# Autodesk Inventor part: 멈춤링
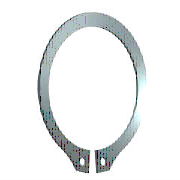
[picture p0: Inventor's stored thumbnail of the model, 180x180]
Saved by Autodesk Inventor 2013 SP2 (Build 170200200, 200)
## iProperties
IsCustomPart: 0
Created: 2009-02
Part Number: 멈춤링
Material: 강, 연강
Description: 리테이닝 링(C형)
Document SubType Name: Modeling
Standard: KS B 1336
Designer: KYOUNG IL JANG
Standards Organization: KS
Language: ko-KR
Size Designation: 22 x 1.2
Categories: <MemberInstance><Categories><Category DisplayName="샤프트 부품" InternalName="7f7aeb1f-a693-4053-b835-cee3144e0d98" Mnemonic="SHFT"><Category DisplayName="써클립" Inter
Density: 1 g/cm^3
Author: KYOUNG IL JANG
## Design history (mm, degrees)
sketch "스케치1"
  geometry: L1 (-6, 0)-(6, 0) reference; L2 (0, 20.189)-(0, -80.536) reference; L3 (-48.09, 0)-(48.09, 0) reference; L4 (-0.5, -21.488)-(-0.5, -25.588); L5 (-0.5, -6.54)-(-0.5, -13.29); L6 (-2.795, 2.7)-(3.672, 2.7); L7 (0.5, -6.54)-(0.5, -13.29); L8 (0.5, -21.488)-(0.5, -25.588); C1 r 1 at (-2, -23.437); C2 r 1 at (2, -23.437); A1 r 10.5 centre (0, -11) between (0.5, -21.488) and (-0.5, -21.488); A2 r 13.025 centre (0, -10.325) between (5.149, -22.289) and (-5.149, -22.289); A3 r 14.597 centre (0, -11) between (-2.318, -25.411) and (-0.5, -25.588); A4 r 2 centre (-2, -23.437) between (-3.97, -23.781) and (-2.318, -25.411); A5 r 2 centre (-5.94, -24.126) between (-3.97, -23.781) and (-5.149, -22.289); A6 r 2 centre (5.94, -24.126) between (5.149, -22.289) and (3.97, -23.781); A7 r 2 centre (2, -23.437) between (2.318, -25.411) and (3.97, -23.781); A8 r 14.597 centre (0, -11) between (0.5, -25.588) and (2.318, -25.411)
  constraints: 16 point on circle, 12 end point, 10 centre point, 9 symmetric about line, 5 point on line, 4 tangent, 3 coincident, 2 horizontal, 1 perpendicular, 1 vertical, 5 other
  dimensions: "d0" = 21 diameter of A1 (= ND); "d1" = 4.1 distance of L4.end L4.start (= SRB2); "d6" = 0.5 distance between parallel lines of L2 L5 (= 0.25 x SD5); "d7" = 2.7 distance between parallel lines of L6 L3 (= SRB1); "d8" = 0.675 distance of A1.centre A2.centre (= 0.25 x SRB1); "d9" = 2 radius of A4 (= SD5); "d10" = 2 radius of A5 (= SD5); "d11" = 1.5 distance from line of L4 A4.centre (= 0.75 x SD5); "d12" = 2 diameter of C1 (= SD5); "d13" = 2 diameter of C2 (= SD5); "d14" = 11 distance from line of A1.centre L1 (= 0.5 x WD)
extrude "본체" new body sketch "스케치1" distance "d2" = 1.2 (= SD); taper "d3" = 0 deg
workaxis "Work Axis1"
workplane "Work Plane1"
body "Solid1"
other parameters: "WD" = 22 (= WDMIN) [user parameter; used in 1 equation term], "SD" = 1.2 [user parameter; used in 1 equation term], "SRB1" = 2.7 [user parameter; used in 2 equation terms], "ND" = 21 [user parameter; used in 1 equation term], "SRB2" = 4.1 [user parameter; used in 1 equation term], "SD5" = 2 [user parameter; used in 6 equation terms], "d15" = 0, "d16" = 0, "d17" = 0, "d41" = 0, "d42" = 0, "WDMIN" = 22 [user parameter; used in 1 equation term], "SD3" = 20.5 [user parameter], "WDMAX" = 24 [user parameter]
